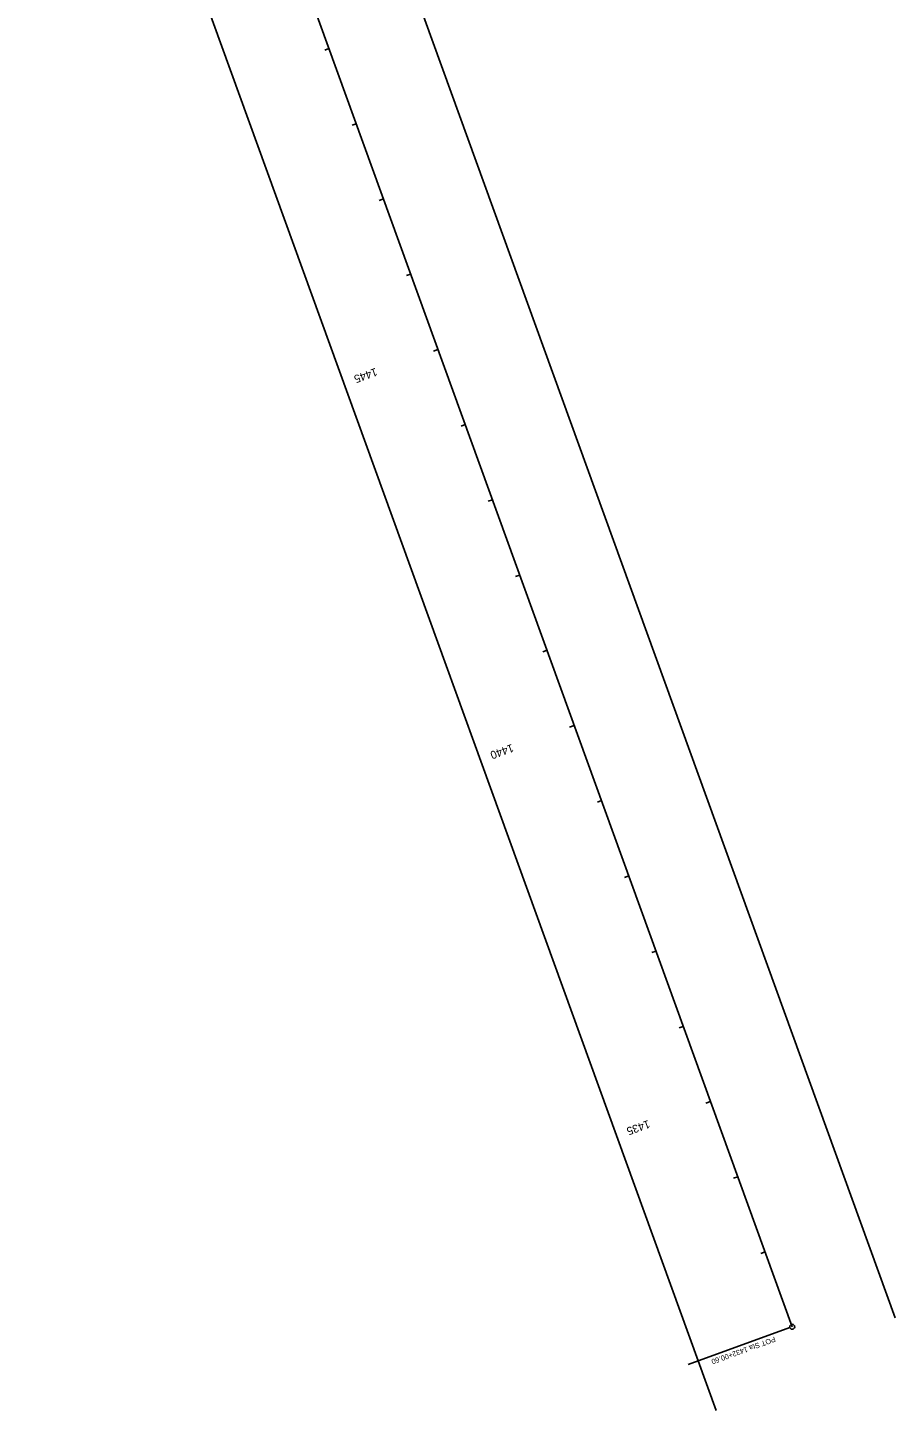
# Model space of a CAD drawing. Extents: x 21596487 to 21601936, y 8263704 to 8275922.
# Drawn here: x 21596676 to 21597761, y 8263704 to 8265433 of the extents above; entities that cross this region are included whole.
import ezdxf

# ---------------------------------------------------------------- set-up
doc = ezdxf.new("R2010")
doc.units = 0
for name, color, linetype in [('dsnXsROWLabelLineExist', 7, 'Continuous'), ('ErosionControl', 7, 'Continuous'), ('Joints', 7, 'Continuous'), ('TC_GranularBackFill', 7, 'Continuous'), ('TC_UnsuitableTypeC', 7, 'Continuous')]:
    doc.layers.add(name, color=color, linetype=linetype)

msp = doc.modelspace()

# ---------------------------------------------------------------- linework, layer by layer
at = {"layer": 'dsnXsROWLabelLineExist'}
for p, q in [((21597761, 8263819.8), (21596911.4, 8266163.9)), ((21597537, 8263704.3), (21596676.4, 8266078.7))]:
    msp.add_line(p, q, dxfattribs=at)
at = {"layer": 'ErosionControl'}
for p, q in [((21597053, 8265406.5), (21597047.8, 8265404.6)), ((21597087, 8265312.5), (21597081.9, 8265310.6)), ((21597121.1, 8265218.5), (21597115.9, 8265216.6)), ((21597155.2, 8265124.5), (21597150, 8265122.6)), ((21597189.3, 8265030.5), (21597183.5, 8265028.4)), ((21597223.3, 8264936.4), (21597218.2, 8264934.6)), ((21597257.4, 8264842.4), (21597252.2, 8264840.6)), ((21597291.5, 8264748.4), (21597286.3, 8264746.5)), ((21597325.6, 8264654.4), (21597320.4, 8264652.5)), ((21597359.6, 8264560.4), (21597353.9, 8264558.3)), ((21597393.7, 8264466.4), (21597388.6, 8264464.5)), ((21597427.8, 8264372.4), (21597422.6, 8264370.5)), ((21597461.9, 8264278.3), (21597456.7, 8264276.5)), ((21597496, 8264184.3), (21597490.8, 8264182.5)), ((21597530, 8264090.3), (21597524.3, 8264088.2)), ((21597564.1, 8263996.3), (21597558.9, 8263994.4)), ((21597598.2, 8263902.3), (21597593, 8263900.4))]:
    msp.add_line(p, q, dxfattribs=at)
at = {"layer": 'TC_GranularBackFill'}
msp.add_line((21597632.1, 8263808.8), (21596793.9, 8266121.3), dxfattribs=at)
at = {"layer": 'TC_UnsuitableTypeC'}
msp.add_line((21597629.1, 8263807.8), (21597502.2, 8263761.8), dxfattribs=at)
msp.add_circle((21597632.1, 8263808.8), 3.12, dxfattribs=at)

# ---------------------------------------------------------------- texts
at = {"layer": 'Joints'}
for s, p in [('1445', (21597111.3, 8265007.5)), ('1440', (21597281.7, 8264537.4)), ('1435', (21597452.1, 8264067.4))]:
    msp.add_text(s, height=10, rotation=199.9238, dxfattribs=at).set_placement(p)
at = {"layer": 'TC_UnsuitableTypeC'}
msp.add_text('POT Sta 1432+00.60', height=6.5, rotation=199.9238, dxfattribs=at).set_placement((21597609.9, 8263796.6))

doc.saveas('drawing.dxf')
